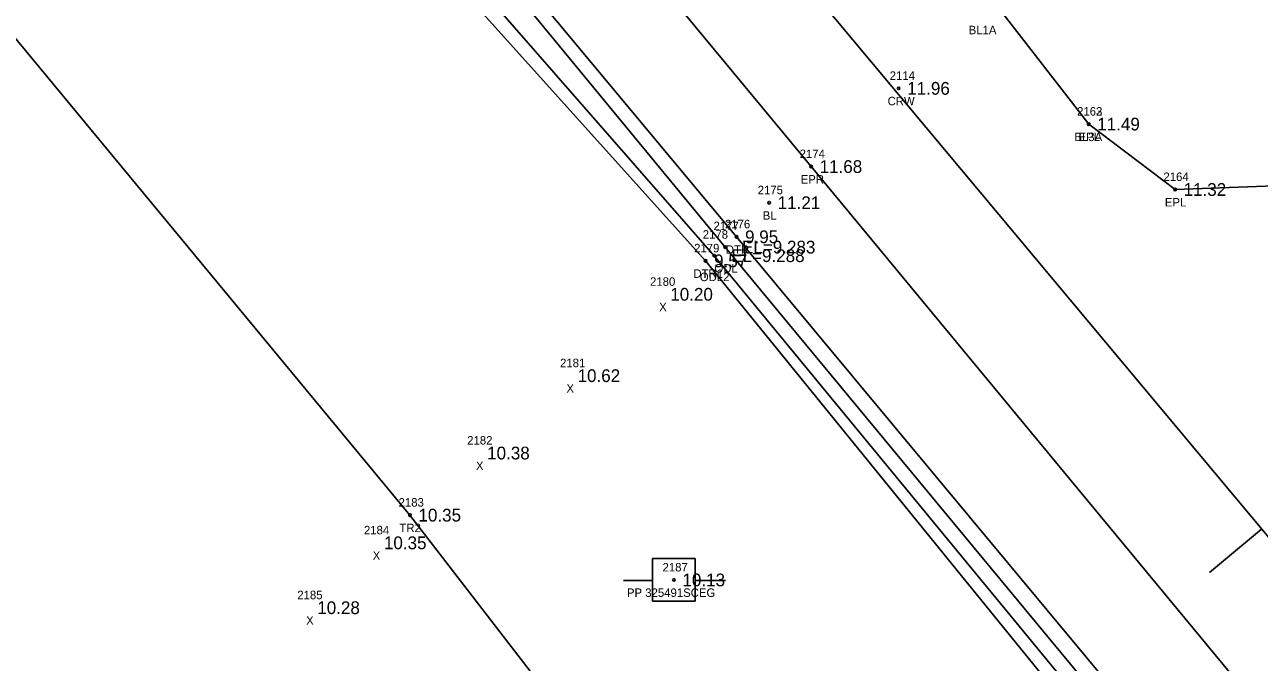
# Model space of a CAD drawing. Extents: x 2042117 to 2045853, y 303080 to 309569.
# Drawn here: x 2044220.7 to 2044366.1, y 304811.9 to 304887 of the extents above; entities that cross this region are included whole.
import ezdxf

# ---------------------------------------------------------------- set-up
doc = ezdxf.new("R2010")
doc.units = 0
for name, color, linetype in [('RD_DTM_BkLn_txCode', 7, 'Continuous'), ('RD_EX_H2O', 7, 'Continuous'), ('RD_EX_H2O_txCode', 7, 'Continuous'), ('RD_EX_Misc_txCode', 7, 'Continuous'), ('RD_EX_Road', 7, 'Continuous'), ('RD_EX_Road_txCode', 7, 'Continuous'), ('RD_EX_TX_H2O_ELEV', 7, 'Continuous'), ('RD_EX_TX_Misc_ELEV', 7, 'Continuous'), ('RD_EX_TX_Road_ELEV', 7, 'Continuous'), ('RD_EX_TX_VEG_ELEV', 7, 'Continuous'), ('RD_EX_UT', 7, 'Continuous'), ('RD_EX_UT_txCode', 7, 'Continuous'), ('RD_EX_VEG', 7, 'Continuous'), ('RD_EX_VEG_txCode', 7, 'Continuous'), ('RD_HC_Cl', 7, 'Continuous'), ('RD_HC_Data_Tic', 7, 'Continuous'), ('RD_HC_Survey_ELEV', 7, 'Continuous'), ('RD_HC_Survey_txCode', 7, 'Continuous'), ('RD_SMD_Locator', 7, 'Continuous')]:
    doc.layers.add(name, color=color, linetype=linetype)

msp = doc.modelspace()

# ---------------------------------------------------------------- linework, layer by layer
at = {"layer": 'RD_EX_H2O'}
for points in [[(2044112.24, 305091.58), (2044175.46, 305015.53), (2044240.61, 304938.74), (2044304.53, 304862.04), (2044368.54, 304785.1), (2044433.36, 304707.39), (2044496.86, 304631.9), (2044519.88, 304601.32), (2044518.57, 304598.19)], [(2044111.06, 305090.52), (2044173.91, 305014.56), (2044239.84, 304937.67), (2044303.17, 304860.83), (2044366.77, 304784.1), (2044432.41, 304706.69), (2044494.93, 304630.14), (2044518.25, 304599.32)], [(2044110.02, 305088.49), (2044170.14, 305011.86), (2044233.99, 304933.5), (2044300.88, 304859.21), (2044363.92, 304781.65), (2044428.82, 304703.43), (2044492.29, 304628.07), (2044516.49, 304597.96), (2044518.57, 304598.19)], [(2044110.63, 305089.46), (2044172, 305013.36), (2044236.2, 304934.93), (2044301.9, 304859.82), (2044365.31, 304782.82), (2044429.99, 304704.43), (2044493.57, 304629.27), (2044517.33, 304598.48)]]:
    msp.add_lwpolyline(points, dxfattribs=at)
at = {"layer": 'RD_EX_Road'}
for points in [[(2043522.11, 305820), (2043547.67, 305789.85), (2043610.72, 305713.32), (2043674.95, 305636.32), (2043738.18, 305559.62), (2043802.42, 305482.71), (2043865.72, 305405.84), (2043929.53, 305328.85), (2043994.13, 305253.28), (2044057.4, 305176.5), (2044121.27, 305100.2), (2044185.29, 305023.54), (2044249.56, 304947.28), (2044313.31, 304870.31), (2044377.09, 304793.29), (2044442, 304716.26), (2044505.92, 304639.55), (2044570.44, 304562.35), (2044634.61, 304485.93), (2044698.46, 304409.27), (2044762.46, 304332.37)], [(2043821.87, 305499.1), (2043885.81, 305423.07), (2043949.56, 305345.93), (2044013.41, 305270.34), (2044077.97, 305194.15), (2044141.4, 305117.67), (2044205.92, 305040.83), (2044269.54, 304964.65), (2044331.73, 304891.04), (2044335.22, 304889.2), (2044346.01, 304875.31), (2044356.18, 304867.61), (2044370.01, 304868.14), (2044386.83, 304866.36), (2044389.44, 304849.53), (2044390.71, 304830.73), (2044393.77, 304818.44), (2044395.5, 304814.18), (2044398.16, 304811.09)]]:
    msp.add_lwpolyline(points, dxfattribs=at)
at = {"layer": 'RD_EX_UT'}
for p, q in [((2044299.64, 304824.15), (2044294.64, 304824.15)), ((2044294.64, 304824.15), (2044294.64, 304819.15)), ((2044299.64, 304819.15), (2044299.64, 304824.15)), ((2044291.21, 304821.58), (2044294.68, 304821.58)), ((2044299.57, 304821.58), (2044303.21, 304821.58)), ((2044294.64, 304819.15), (2044299.64, 304819.15))]:
    msp.add_line(p, q, dxfattribs=at)
at = {"layer": 'RD_EX_VEG'}
msp.add_lwpolyline([(2043442.97, 305737.07), (2043459.87, 305757.29), (2043500.33, 305735.55), (2043510.29, 305716.16), (2043558.94, 305666.15), (2043625.65, 305592.92), (2043688.91, 305518.94), (2043753.11, 305437.19), (2043818.03, 305364.7), (2043877.83, 305282.82), (2043938.63, 305211.62), (2044011.48, 305138.99), (2044075.86, 305057.44), (2044138.75, 304984.38), (2044203.27, 304905.13), (2044266.06, 304829.27), (2044328.58, 304748.23), (2044394.11, 304672.51), (2044456.79, 304595.02), (2044489.64, 304560.38)], dxfattribs=at)
at = {"layer": 'RD_HC_Cl'}
msp.add_line((2043284.3, 306123.24), (2045221.31, 303804), dxfattribs=at)
at = {"layer": 'RD_HC_Data_Tic'}
msp.add_line((2044366.38, 304827.63), (2044360.24, 304822.5), dxfattribs=at)
at = {"layer": 'RD_SMD_Locator'}
for centre in [(2044323.63, 304879.52), (2044346.01, 304875.31), (2044346.01, 304875.31), (2044313.31, 304870.31), (2044356.18, 304867.61), (2044308.37, 304866.05), (2044304.53, 304862.04), (2044301.9, 304859.82), (2044303.17, 304860.83), (2044300.88, 304859.21), (2044266.06, 304829.27), (2044297.15, 304821.64)]:
    msp.add_circle(centre, 0.15, dxfattribs=at)

# ---------------------------------------------------------------- texts
at = {"layer": 'RD_DTM_BkLn_txCode'}
for s, p in [('BL1A', (2044331.87, 304885.89)), ('2163', (2044344.64, 304876.31)), ('BL3A', (2044344.32, 304873.31)), ('2175', (2044307.02, 304867.05)), ('BL', (2044307.61, 304864.05))]:
    msp.add_text(s, height=1, dxfattribs=at).set_placement(p)
at = {"layer": 'RD_EX_H2O_txCode'}
for s, p in [('2178', (2044300.55, 304861.82)), ('2177', (2044301.82, 304862.83)), ('2176', (2044303.16, 304863.04)), ('2179', (2044299.53, 304860.21)), ('DTR', (2044303.26, 304860.04)), ('ODL', (2044301.92, 304857.83)), ('DTR1', (2044299.44, 304857.21)), ('ODL2', (2044300.2, 304856.82))]:
    msp.add_text(s, height=1, dxfattribs=at).set_placement(p)
at = {"layer": 'RD_EX_Misc_txCode'}
for s, p in [('2180', (2044294.34, 304856.27)), ('X', (2044295.41, 304853.27)), ('2181', (2044283.74, 304846.69)), ('X', (2044284.49, 304843.69)), ('2182', (2044272.8, 304837.58)), ('X', (2044273.83, 304834.58)), ('2184', (2044260.64, 304827.01)), ('X', (2044261.67, 304824.01)), ('2185', (2044252.79, 304819.37)), ('X', (2044253.83, 304816.37))]:
    msp.add_text(s, height=1, dxfattribs=at).set_placement(p)
at = {"layer": 'RD_EX_Road_txCode'}
for s, p in [('2162', (2044344.64, 304876.31)), ('EPL', (2044344.81, 304873.31)), ('2174', (2044311.96, 304871.31)), ('EPR', (2044312.08, 304868.31)), ('2164', (2044354.81, 304868.61)), ('EPL', (2044354.98, 304865.61))]:
    msp.add_text(s, height=1, dxfattribs=at).set_placement(p)
at = {"layer": 'RD_EX_TX_H2O_ELEV'}
for s, p in [('9.95', (2044305.53, 304861.29)), ('EL=9.283', (2044305.17, 304860.08)), ('9.57', (2044301.88, 304858.46)), ('EL=9.288', (2044303.9, 304859.07))]:
    msp.add_text(s, height=1.5, dxfattribs=at).set_placement(p)
at = {"layer": 'RD_EX_TX_Misc_ELEV'}
for s, p in [('11.49', (2044347.01, 304874.56)), ('11.21', (2044309.37, 304865.3)), ('10.20', (2044296.72, 304854.52)), ('10.62', (2044285.8, 304844.94)), ('10.38', (2044275.15, 304835.83)), ('10.35', (2044262.99, 304825.26)), ('10.28', (2044255.14, 304817.62))]:
    msp.add_text(s, height=1.5, dxfattribs=at).set_placement(p)
at = {"layer": 'RD_EX_TX_Road_ELEV'}
for s, p in [('11.49', (2044347.01, 304874.56)), ('11.68', (2044314.31, 304869.56)), ('11.32', (2044357.18, 304866.86))]:
    msp.add_text(s, height=1.5, dxfattribs=at).set_placement(p)
at = {"layer": 'RD_EX_TX_VEG_ELEV'}
msp.add_text('10.35', height=1.5, dxfattribs=at).set_placement((2044267.06, 304828.52))
at = {"layer": 'RD_EX_UT_txCode'}
for s, p in [('2187', (2044295.81, 304822.64)), ('PP 325491SCEG', (2044291.62, 304819.64))]:
    msp.add_text(s, height=1, dxfattribs=at).set_placement(p)
at = {"layer": 'RD_EX_VEG_txCode'}
for s, p in [('2183', (2044264.72, 304830.27)), ('TR2', (2044264.82, 304827.27))]:
    msp.add_text(s, height=1, dxfattribs=at).set_placement(p)
at = {"layer": 'RD_HC_Survey_ELEV'}
for s, p in [('11.96', (2044324.63, 304878.77)), ('10.13', (2044298.15, 304820.89))]:
    msp.add_text(s, height=1.5, dxfattribs=at).set_placement(p)
at = {"layer": 'RD_HC_Survey_txCode'}
for s, p in [('2114', (2044322.57, 304880.52)), ('CRW', (2044322.32, 304877.52))]:
    msp.add_text(s, height=1, dxfattribs=at).set_placement(p)

doc.saveas('drawing.dxf')
